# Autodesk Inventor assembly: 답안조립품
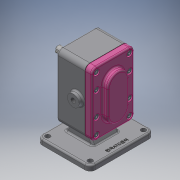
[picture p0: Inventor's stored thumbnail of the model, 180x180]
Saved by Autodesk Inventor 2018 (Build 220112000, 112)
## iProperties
Created: 2020-04
Part Number: 답안조립품
Material: 일반
Document SubType Name: Assembly
Designer: USER
Author: USER
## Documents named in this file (11)
- C:\Users\USER\Desktop\700407V1002\답안조립품.iam
- C:\Users\USER\Desktop\700407V1002\본체.ipt
- C:\Users\USER\Desktop\700407V1002\개스킷.ipt
- C:\Users\USER\Desktop\700407V1002\메인축.ipt
- C:\Users\USER\Desktop\700407V1002\베어링부시.ipt
- C:\Users\USER\Desktop\700407V1002\볼트 M5.ipt
- C:\Users\USER\Desktop\700407V1002\서브축.ipt
- C:\Users\USER\Desktop\700407V1002\스퍼기어.ipt
- C:\Users\USER\Desktop\700407V1002\오일 실 16 28 7.ipt
- C:\Users\USER\Desktop\700407V1002\커버.ipt
- C:\Users\USER\Desktop\700407V1002\키 6 x 6 x 18.ipt
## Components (1 placed, 1 different names)
1. 개스킷:1
